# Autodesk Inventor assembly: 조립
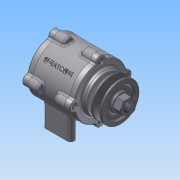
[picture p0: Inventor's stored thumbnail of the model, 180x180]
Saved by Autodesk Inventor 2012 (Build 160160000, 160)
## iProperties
Created: 2015-03
Part Number: 조립
Document SubType Name: Assembly
Designer: net
Author: net
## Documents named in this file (11)
- C:\Users\net\Desktop\450305V1051\조립.iam
- C:\Users\net\Desktop\450305V1051\본체.ipt
- C:\Users\net\Desktop\450305V1051\커버.ipt
- C:\Users\net\Desktop\450305V1051\커버2.ipt
- C:\Users\net\Desktop\450305V1051\베어링 6204.ipt
- C:\Users\net\Desktop\450305V1051\오일실.ipt
- C:\Users\net\Desktop\450305V1051\축.ipt
- C:\Users\net\Desktop\450305V1051\키(4 x 4 x 12).ipt
- C:\Users\net\Desktop\450305V1051\V벨트풀리.ipt
- C:\Users\net\Desktop\450305V1051\너트 M12x1.25.ipt
- C:\Users\net\Desktop\450305V1051\M 4 x 12.ipt
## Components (14 placed, 6 different names)
1. KS B 2023 6204 - 20 x 47 x 14:1
2. KS B 2023 6204 - 20 x 47 x 14:2
3. KS B 2804 D D - 20 32 8:1
4. KS B 1311 (I) 4 x 4 x 12:1 — 각도:1, 각도:2
5. 그루브 풀리1:1 — 각도:2
6. KS B 1012 클래스 1 일반 - 미터 M12x1.25:1
7. KS B 1003 - 미터 M 4 x 12:2
8. KS B 1003 - 미터 M 4 x 12:3
9. KS B 1003 - 미터 M 4 x 12:4
10. KS B 1003 - 미터 M 4 x 12:5
11. KS B 1003 - 미터 M 4 x 12:1
12. KS B 1003 - 미터 M 4 x 12:6
13. KS B 1003 - 미터 M 4 x 12:7
14. KS B 1003 - 미터 M 4 x 12:8
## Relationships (2: Angle 2)
- 각도:1 [Angle]: KS B 1311 (I) 4 x 4 x 12:1
- 각도:2 [Angle]: KS B 1311 (I) 4 x 4 x 12:1 ↔ 그루브 풀리1:1
